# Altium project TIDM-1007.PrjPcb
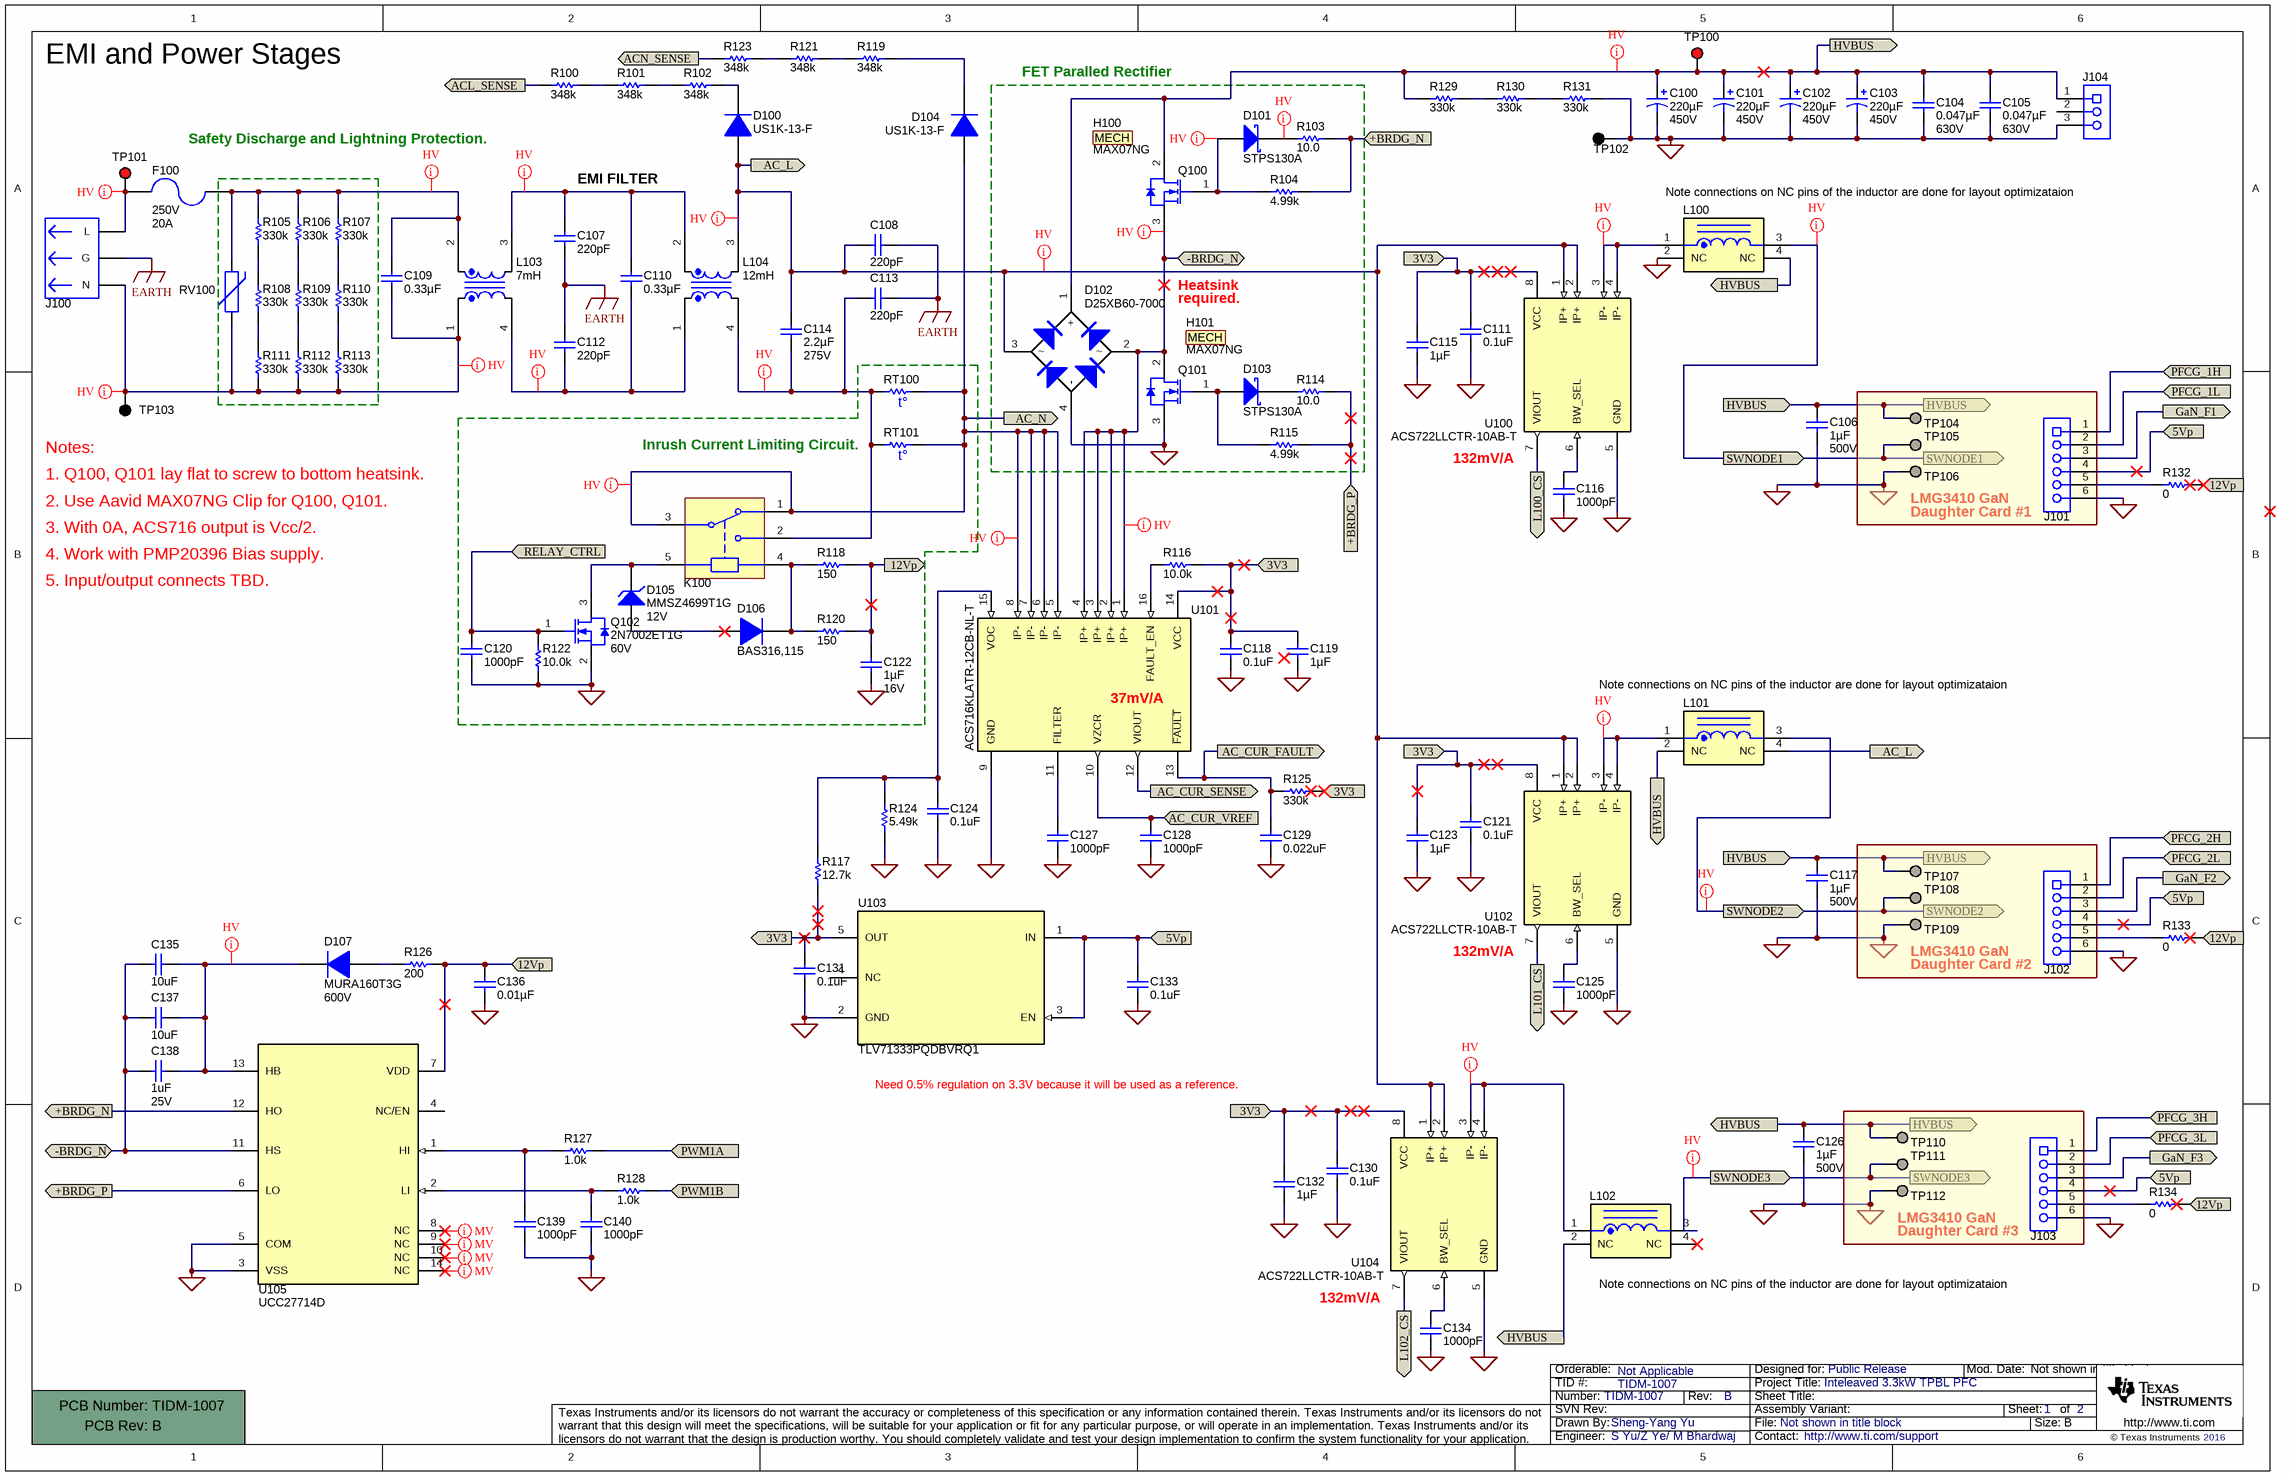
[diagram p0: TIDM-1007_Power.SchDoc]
TID: TIDM-1007; TechSupport: http://www.ti.com/support; SCH_Rev: B; PRJ_Title: Inteleaved 3.3kW TPBL PFC; PRJ_Number: TIDM-1007; PRJ_Engineer: S Yu/Z Ye/ M Bhardwaj; PRJ_Customer: Public Release; PCB_Rev: B; PCB_Layout: S Yu; EVM_orderable: Not Applicable; CopyrightYear: 2016
2 sheets, 193 parts. Net scope: flat (ports and power ports of the same name join across sheets).
Board file: TIDM-1007_PCB.PcbDoc
Sheets:
  TIDM-1007_Power.SchDoc
  TIDM-1007_Control.SchDoc

## Sheet TIDM-1007_Power.SchDoc
size 431 x 279 mm; Date: Not shown in title block; ApprovedBy: Not shown in title block; CheckedBy: Not shown in title block; Author: Not shown in title block; CompanyName: Not shown in title block; DrawnBy: Sheng-Yang Yu; Engineer: Not shown in title block; Organization: Not shown in title block; Address1: Not shown in title block; Address2: Not shown in title block; Address3: Not shown in title block; Address4: Not shown in title block; DocumentNumber: 1; Revision: Use project parameter SCH_Rev; SheetNumber: 1; SheetTotal: 2; PageSetup: Record=PageOptions¦CenterHorizontal=True¦CenterVertical=True¦PrintScale=1.00¦XCorrection=1.00¦YCorrection=1.00¦PrintKind=0¦BorderSize=5000000¦LeftOffset=0¦BottomOffset=0¦Orientation=2¦PaperLength=1000¦PaperWidth=1000¦Scale=100¦PaperSource=15¦PrintQuality=600¦MediaType=1¦DitherType=10¦PaperKind=Letter¦PrintScaleMode=1

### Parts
!PCB100  Printed Circuit Board  (value not drawn)  (mechanical)
C100  ValueDisplayed: 220µF  Value2: 450V  [KMW_2200x4000]  (hidden comment: EKMW451VSN221MP40S)
C101  ValueDisplayed: 220µF  Value2: 450V  [KMW_2200x4000]  (hidden comment: EKMW451VSN221MP40S)
C102  ValueDisplayed: 220µF  Value2: 450V  [KMW_2200x4000]  (hidden comment: EKMW451VSN221MP40S)
C103  ValueDisplayed: 220µF  Value2: 450V  [KMW_2200x4000]  (hidden comment: EKMW451VSN221MP40S)
C104  ValueDisplayed: 0.047µF  Value2: 630V  [1210_220]  (hidden comment: GRM32DR72J473KW01L)
C105  ValueDisplayed: 0.047µF  Value2: 630V  [1210_220]  (hidden comment: GRM32DR72J473KW01L)
C106  ValueDisplayed: 1µF  Value2: 500V  [B58031I_1084x785x450]  (hidden comment: B58031I5105M002)
C107  ValueDisplayed: 220pF  [DE1_600x400x900]  (hidden comment: DE1B3RA101KN4AN01F)
C108  ValueDisplayed: 220pF  [DE1_600x400x900]  (hidden comment: DE1B3RA101KN4AN01F)
C109  ValueDisplayed: 0.33µF  [B32923_15mm]  (hidden comment: B32923C3334M)
C110  ValueDisplayed: 0.33µF  [B32923_15mm]  (hidden comment: B32923C3334M)
C111  ValueDisplayed: 0.1uF  [0402]  (hidden comment: GRM155R70J104KA01D)
C112  ValueDisplayed: 220pF  [DE1_600x400x900]  (hidden comment: DE1B3RA101KN4AN01F)
C113  ValueDisplayed: 220pF  [DE1_600x400x900]  (hidden comment: DE1B3RA101KN4AN01F)
C114  ValueDisplayed: 2.2µF  Value2: 275V  [WCAP-FTX2_2600x1500x2500]  (hidden comment: 890324026034)
C115  ValueDisplayed: 1µF  [0603]  (hidden comment: GRM185R60J105KE26D)
C116  ValueDisplayed: 1000pF  [0603]  (hidden comment: 06035A102KAT2A)
C117  ValueDisplayed: 1µF  Value2: 500V  [B58031I_1084x785x450]  (hidden comment: B58031I5105M002)
C118  ValueDisplayed: 0.1uF  [0402]  (hidden comment: GRM155R70J104KA01D)
C119  ValueDisplayed: 1µF  [0603]  (hidden comment: GRM185R60J105KE26D)
C120  ValueDisplayed: 1000pF  [0603]  (hidden comment: GRM188R71C102KA01D)
C121  ValueDisplayed: 0.1uF  [0402]  (hidden comment: GRM155R70J104KA01D)
C122  ValueDisplayed: 1µF  Value2: 16V  [0805_HV]  (hidden comment: 0805YD105KAT2A)
C123  ValueDisplayed: 1µF  [0603]  (hidden comment: GRM185R60J105KE26D)
C124  ValueDisplayed: 0.1uF  [0402]  (hidden comment: GRM155R70J104KA01D)
C125  ValueDisplayed: 1000pF  [0603]  (hidden comment: 06035A102KAT2A)
C126  ValueDisplayed: 1µF  Value2: 500V  [B58031I_1084x785x450]  (hidden comment: B58031I5105M002)
C127  ValueDisplayed: 1000pF  [0402]  (hidden comment: GRM155R60J102KA01D)
C128  ValueDisplayed: 1000pF  [0402]  (hidden comment: GRM155R60J102KA01D)
C129  ValueDisplayed: 0.022uF  [0402]  (hidden comment: GRM155R70J223KA01D)
C130  ValueDisplayed: 0.1uF  [0402]  (hidden comment: GRM155R70J104KA01D)
C131  ValueDisplayed: 0.1uF  [0402]  (hidden comment: GRM155R70J104KA01D)
C132  ValueDisplayed: 1µF  [0603]  (hidden comment: GRM185R60J105KE26D)
C133  ValueDisplayed: 0.1uF  [0402]  (hidden comment: GRM155R70J104KA01D)
C134  ValueDisplayed: 1000pF  [0603]  (hidden comment: 06035A102KAT2A)
C135  ValueDisplayed: 10uF  [0805_HV]  (hidden comment: 0805YD106MAT2A)
C136  ValueDisplayed: 0.01µF  [0603]  (hidden comment: C0603X103K5RACTU)
C137  ValueDisplayed: 10uF  [0805_HV]  (hidden comment: 0805YD106MAT2A)
C138  ValueDisplayed: 1uF  Value2: 25V  [0603]  (hidden comment: C1608X7R1E105K080AB)
C139  ValueDisplayed: 1000pF  [0603]  (hidden comment: 06035A102KAT2A)
C140  ValueDisplayed: 1000pF  [0603]  (hidden comment: 06035A102KAT2A)
D100  US1K-13-F  [SMA]
D101  STPS130A  [SMA]
D102  D25XB60-7000  [5S]
D103  STPS130A  [SMA]
D104  US1K-13-F  [SMA]
D105  MMSZ4699T1G  value 12V  [SOD-123]
D106  BAS316,115  [sod-323]
D107  MURA160T3G  value 600V  [SMA]
F100  VAC_V: 250V  Irating_A: 20A  [FUSE_0325_Verical]  (hidden comment: 0325020.MXP)
H100  MAX07NG  (mechanical)
H101  MAX07NG  (mechanical)
J100  703W-00/54  [CONN_QUALTEK-703W-0054]  (value not drawn)  (mechanical)
J101  0448120024  [Molex_0448120024]  (value not drawn)
J102  0448120024  [Molex_0448120024]  (value not drawn)
J103  0448120024  [Molex_0448120024]  (value not drawn)
J104  282856-3  [TE_282856-3]  (value not drawn)
K100  875B-1CC-F-S-12VDC  [RELAY_875]  (value not drawn)
L100  G164005LF  [IND_7840-09-0014]  (value not drawn)
L101  G164005LF  [IND_7840-09-0014]  (value not drawn)
L102  G164005LF  [IND_7840-09-0014]  (value not drawn)
L103  ValueDisplayed: 7mH  [WE-CMBNC_XL]  (hidden comment: 7448051507)
L104  ValueDisplayed: 12mH  [WE-CMBNC_XL]  (hidden comment: 7448051012)
Q100  STY145N65M5  [TO-247]  (value not drawn)
Q101  STY145N65M5  [TO-247]  (value not drawn)
Q102  2N7002ET1G  value 60V  [SOT-23]
R100  value 348k  [0805_HV]  (hidden comment: RT0805BRD07348KL)
R101  value 348k  [0805_HV]  (hidden comment: RT0805BRD07348KL)
R102  value 348k  [0805_HV]  (hidden comment: RT0805BRD07348KL)
R103  ValueDisplayed: 10.0  [0805_HV]  (hidden comment: CRCW080510R0FKEA)
R104  ValueDisplayed: 4.99k  [0805_HV]  (hidden comment: ERJ-6ENF4991V)
R105  ValueDisplayed: 330k  [1206]  (hidden comment: CRCW1206330KJNEA)
R106  ValueDisplayed: 330k  [1206]  (hidden comment: CRCW1206330KJNEA)
R107  ValueDisplayed: 330k  [1206]  (hidden comment: CRCW1206330KJNEA)
R108  ValueDisplayed: 330k  [1206]  (hidden comment: CRCW1206330KJNEA)
R109  ValueDisplayed: 330k  [1206]  (hidden comment: CRCW1206330KJNEA)
R110  ValueDisplayed: 330k  [1206]  (hidden comment: CRCW1206330KJNEA)
R111  ValueDisplayed: 330k  [1206]  (hidden comment: CRCW1206330KJNEA)
R112  ValueDisplayed: 330k  [1206]  (hidden comment: CRCW1206330KJNEA)
R113  ValueDisplayed: 330k  [1206]  (hidden comment: CRCW1206330KJNEA)
R114  ValueDisplayed: 10.0  [0805_HV]  (hidden comment: CRCW080510R0FKEA)
R115  ValueDisplayed: 4.99k  [0805_HV]  (hidden comment: ERJ-6ENF4991V)
R116  value 10.0k  [0402]  (hidden comment: CRCW040210K0FKED)
R117  value 12.7k  [0402]  (hidden comment: CRCW040212K7FKED)
R118  ValueDisplayed: 150  [1206]  (hidden comment: CRCW1206150RJNEA)
R119  value 348k  [0805_HV]  (hidden comment: RT0805BRD07348KL)
R120  ValueDisplayed: 150  [1206]  (hidden comment: CRCW1206150RJNEA)
R121  value 348k  [0805_HV]  (hidden comment: RT0805BRD07348KL)
R122  value 10.0k  [0603]  (hidden comment: RC0603FR-0710KL)
R123  value 348k  [0805_HV]  (hidden comment: RT0805BRD07348KL)
R124  value 5.49k  [0402]  (hidden comment: CRCW04025K49FKED)
R125  value 330k  [0402]  (hidden comment: CRCW0402330KJNED)
R126  value 200  [0603]  (hidden comment: CRCW0603200RFKEA)
R127  value 1.0k  [0402]  (hidden comment: CRCW04021K00JNED)
R128  value 1.0k  [0402]  (hidden comment: CRCW04021K00JNED)
R129  ValueDisplayed: 330k  [1206]  (hidden comment: CRCW1206330KJNEA)
R130  ValueDisplayed: 330k  [1206]  (hidden comment: CRCW1206330KJNEA)
R131  ValueDisplayed: 330k  [1206]  (hidden comment: CRCW1206330KJNEA)
R132  ValueDisplayed: 0  [0603]  (hidden comment: CRCW06030000Z0EA)
R133  ValueDisplayed: 0  [0603]  (hidden comment: CRCW06030000Z0EA)
R134  ValueDisplayed: 0  [0603]  (hidden comment: CRCW06030000Z0EA)
RT100  B59751B0120A070  [TDK_B751]  (value not drawn)
RT101  B59751B0120A070  [TDK_B751]  (value not drawn)
RV100  S10K275E2  [VAR_S10K275E2]  (value not drawn)
TP100  Vo  [Keystone5000]  (value not drawn)
TP101  L  [Keystone5000]  (value not drawn)
TP102  PGND_PFC  [Keystone5001]  (value not drawn)
TP103  N  [Keystone5001]  (value not drawn)
TP104  Suggest using a net name here  [Mill-Max_0312-0-15-15-34-27-10-0]  (value not drawn)
TP105  Suggest using a net name here  [Mill-Max_0312-0-15-15-34-27-10-0]  (value not drawn)
TP106  Suggest using a net name here  [Mill-Max_0312-0-15-15-34-27-10-0]  (value not drawn)
TP107  Suggest using a net name here  [Mill-Max_0312-0-15-15-34-27-10-0]  (value not drawn)
TP108  Suggest using a net name here  [Mill-Max_0312-0-15-15-34-27-10-0]  (value not drawn)
TP109  Suggest using a net name here  [Mill-Max_0312-0-15-15-34-27-10-0]  (value not drawn)
TP110  Suggest using a net name here  [Mill-Max_0312-0-15-15-34-27-10-0]  (value not drawn)
TP111  Suggest using a net name here  [Mill-Max_0312-0-15-15-34-27-10-0]  (value not drawn)
TP112  Suggest using a net name here  [Mill-Max_0312-0-15-15-34-27-10-0]  (value not drawn)
U100  ACS722LLCTR-10AB-T  [SOIC-8]
U101  ACS716KLATR-12CB-NL-T  [SOIC-16]
U102  ACS722LLCTR-10AB-T  [SOIC-8]
U103  TLV71333PQDBVRQ1  [DBV0005A_N]
U104  ACS722LLCTR-10AB-T  [SOIC-8]
U105  UCC27714D  [D0014A_N]

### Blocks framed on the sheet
Inrush Current Limiting Circuit.: C120 C122 D105 D106 K100 Q102 R118 R120 R122 RT100 RT101

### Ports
3V3 (in), 3V3 (out), 5Vp (in), 12Vp (in), 12Vp (out), +BRDG_N, +BRDG_P, +BRDG_P (in), -BRDG_N (bidir), AC_CUR_FAULT, AC_CUR_SENSE, AC_CUR_VREF, AC_L, AC_N, ACL_SENSE (out), ACN_SENSE (out), GaN_F1 (out), GaN_F2 (out), GaN_F3 (out), HVBUS (in), HVBUS (out), L100_CS (out), L101_CS (out), L102_CS (out), PFCG_1H (in), PFCG_1L (in), PFCG_2H (in), PFCG_2L (in), PFCG_3H (in), PFCG_3L (in), PWM1A (in), PWM1B (in), RELAY_CTRL (in), SWNODE1 (out), SWNODE2 (out), SWNODE3 (out)

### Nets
EARTH: C107.2 C108.2 C112.1 C113.2 J100.3(G)
PGND: C100.2(-) C101.2(-) C102.2(-) C103.2(-) C104.1 C105.1 C106.1 C111.2 C115.2 C116.2 C117.1 C118.2 C119.2 C120.2 C121.2 C122.1 C123.2 C124.2 C125.2 C126.1 C127.2 C128.2 C129.1 C130.2 C131.2 C132.2 C133.2 C134.2 C136.2 C139.2 C140.2 D102.4(-) J101.6 J102.6 J103.6 J104.3 L100.2(NC) Q101.3(S) Q102.2(S) R122.1 R124.1 R131.1 TP102.1 TP106.1 TP109.1 TP112.1 U100.5(GND) U101.9(GND) U102.5(GND) U103.2(GND) U104.5(GND) U105.3(VSS) U105.5(COM)
3V3: C111.1 C115.1 C118.1 C119.1 C121.1 C123.1 C130.1 C131.1 C132.1 R116.2 R117.2 R125.1 U100.8(VCC) U101.14(VCC) U102.8(VCC) U103.5(OUT) U104.8(VCC) ; port 3V3
5Vp: C133.1 J101.4 J102.4 J103.4 U103.1(IN) U103.3(EN) ; port 5Vp
12Vp: C122.2 C136.1 R118.2 R120.2 R126.2 R132.2 R133.2 R134.2 U105.7(VDD) ; port 12Vp
+BRDG_N: R103.2 R104.2 U105.12(HO) ; port +BRDG_N
+BRDG_P: R114.2 R115.2 U105.6(LO) ; port +BRDG_P
-BRDG_N: C135.2 C137.2 C138.1 D102.2 Q100.3(S) Q101.2(D) U101.1(IP+) U101.2(IP+) U101.3(IP+) U101.4(IP+) U105.11(HS) ; port -BRDG_N
AC_CUR_FAULT: C129.2 R125.2 U101.13(~{FAULT}) ; port AC_CUR_FAULT
AC_CUR_SENSE: U101.12(VIOUT) ; port AC_CUR_SENSE
AC_CUR_VREF: C128.1 U101.10(VZCR) ; port AC_CUR_VREF
AC_L: C108.1 C114.1 D100.2(A) D102.3 L101.4(NC) L104.3 U100.1(IP+) U100.2(IP+) U102.1(IP+) U102.2(IP+) U104.1(IP+) U104.2(IP+) ; port AC_L
AC_N: D104.2(A) K100.1 K100.3 RT100.2 RT101.2 U101.5(IP-) U101.6(IP-) U101.7(IP-) U101.8(IP-) ; port AC_N
ACL_SENSE: R100.1 ; port ACL_SENSE
ACN_SENSE: R123.1 ; port ACN_SENSE
GaN_F1: J101.3 ; port GaN_F1
GaN_F2: J102.3 ; port GaN_F2
GaN_F3: J103.3 ; port GaN_F3
HVBUS: C100.1(+) C101.1(+) C102.1(+) C103.1(+) C104.2 C105.2 C106.2 C117.2 C126.2 D102.1(+) J104.1 L100.4(NC) L101.2(NC) L102.2(NC) Q100.2(D) R129.2 TP100.1 TP104.1 TP107.1 TP110.1 ; port HVBUS
L100_CS: U100.7(VIOUT) ; port L100_CS
L101_CS: U102.7(VIOUT) ; port L101_CS
L102_CS: U104.7(VIOUT) ; port L102_CS
PFCG_1H: J101.1 ; port PFCG_1H
PFCG_1L: J101.2 ; port PFCG_1L
PFCG_2H: J102.1 ; port PFCG_2H
PFCG_2L: J102.2 ; port PFCG_2L
PFCG_3H: J103.1 ; port PFCG_3H
PFCG_3L: J103.2 ; port PFCG_3L
PWM1A: R127.2 ; port PWM1A
PWM1B: R128.2 ; port PWM1B
RELAY_CTRL: C120.1 Q102.1(G) R122.2 ; port RELAY_CTRL
SWNODE1: L100.3 TP105.1 ; port SWNODE1
SWNODE2: L101.3 TP108.1 ; port SWNODE2
SWNODE3: L102.3 TP111.1 ; port SWNODE3
NetC107_1: C107.1 C110.1 L103.3 L104.2
NetC109_1: C109.1 F100.1 L103.2 R105.2 R106.2 R107.2 RV100.2
NetC109_2: C109.2 J100.2(N) L103.1 R111.1 R112.1 R113.1 RV100.1 TP103.1
NetC110_2: C110.2 C112.2 L103.4 L104.1
NetC113_1: C113.1 C114.2 K100.2 L104.4 RT100.1 RT101.1
NetC116_1: C116.1 U100.6(BW_SEL)
NetC124_1: C124.1 R117.1 R124.2 U101.15(VOC)
NetC125_1: C125.1 U102.6(BW_SEL)
NetC127_1: C127.1 U101.11(FILTER)
NetC134_1: C134.1 U104.6(BW_SEL)
NetC135_1: C135.1 C137.1 C138.2 D107.1(K) U105.13(HB)
NetC139_1: C139.1 R127.1 U105.1(HI)
NetC140_1: C140.1 R128.1 U105.2(LI)
NetD100_1: D100.1(K) R102.2
NetD101_1: D101.1(K) R103.1
NetD101_2: D101.2(A) Q100.1(G) R104.1
NetD103_1: D103.1(K) R114.1
NetD103_2: D103.2(A) Q101.1(G) R115.1
NetD104_1: D104.1(K) R119.2
NetD105_1: D105.1(K) K100.5 Q102.3(D)
NetD105_2: D105.2(A) D106.2(A)
NetD106_1: D106.1(K) K100.4 R118.1 R120.1
NetD107_2: D107.2(A) R126.1
NetF100_2: F100.2 J100.1(L) TP101.1
NetJ101_5: J101.5 R132.1
NetJ102_5: J102.5 R133.1
NetJ103_5: J103.5 R134.1
NetL100_1: L100.1 U100.3(IP-) U100.4(IP-)
NetL101_1: L101.1 U102.3(IP-) U102.4(IP-)
NetL102_1: L102.1 U104.3(IP-) U104.4(IP-)
NetR100_2: R100.2 R101.1
NetR101_2: R101.2 R102.1
NetR105_1: R105.1 R108.2
NetR106_1: R106.1 R109.2
NetR107_1: R107.1 R110.2
NetR108_1: R108.1 R111.2
NetR109_1: R109.1 R112.2
NetR110_1: R110.1 R113.2
NetR116_1: R116.1 U101.16(FAULT_EN)
NetR119_1: R119.1 R121.2
NetR121_1: R121.1 R123.2
NetR129_1: R129.1 R130.2
NetR130_1: R130.1 R131.2

Not connected (* = marked no-connect by the designer): J104 2; L102 4(NC)*; U103 4(NC); U105 4(NC/EN) 8(NC)* 9(NC)* 10(NC)* 14(NC)*

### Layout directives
net class HV: -BRDG_N, AC_L, AC_N, HVBUS, NetC107_1, NetC109_1, NetC109_2, NetC110_2, NetC113_1, NetC135_1, NetD101_1, NetD101_2, NetF100_2, NetL100_1, NetL101_1, NetL102_1, SWNODE1, SWNODE2, SWNODE3
net class MV: NetU105_8, NetU105_9, NetU105_10, NetU105_14

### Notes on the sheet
- EMI and Power Stages
- FET Paralled Rectifier
- Safety Discharge and Lightning Protection.
- (near C107) EMI FILTER
- Note connections on NC pins of the inductor are done for layout optimizataion
- Heatsink
- (near H101) required.
- (near TP103) Notes:
- 1. Q100, Q101 lay flat to screw to bottom heatsink.
- (near U100) 132mV/A
- (near TP106) LMG3410 GaN
- 3. With 0A, ACS716 output is Vcc/2.
- 4. Work with PMP20396 Bias supply.
- 2. Use Aavid MAX07NG Clip for Q100, Q101.
- Daughter Card #1
- 5. Input/output connects TBD.
- (near U101) 37mV/A
- (near L101) Note connections on NC pins of the inductor are done for layout optimizataion
- (near U102) 132mV/A
- (near TP109) LMG3410 GaN
- Daughter Card #2
- Need 0.5% regulation on 3.3V because it will be used as a reference.
- (near TP112) LMG3410 GaN
- Daughter Card #3
- (near U104) 132mV/A
- (near L102) Note connections on NC pins of the inductor are done for layout optimizataion

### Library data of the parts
!PCB100 = PCB: Manufacturer: Any; SymbolCreator: a0412235
C100-C103 = EKMW451VSN221MP40S: CAP, AL, 220 µF, 450 V, +/- 20%, TH; Manufacturer: Chemi-Con; Polarized: Y; CompType: Capacitor; Value: 220uF; U/M: EA; Cap_F: 0.00022; Tolerance_%: 20; Value1: Unknown; VDC_V: 450; IRMS_A: 1.15; TaMin_C: -25; TaMax_C: 105; Cap_Case: 22x40mm; AEC Category: Q200; AEC Qualified: N
C104 C105 = GRM32DR72J473KW01L: CAP, CERM, 0.047 µF, 630 V, +/- 10%, X7R, 1210; Manufacturer: MuRata; Polarized: N; CompType: Capacitor; Value: 0.047uF; U/M: EA; Cap_F: 0.000000047; Tolerance_%: 10; Value1: Unknown; VDC_V: 630; TaMin_C: -55; TaMax_C: 125; Cap_Case: 1210; SizeArea_mm2: 8; SizeAreaWB_mm2: 14.7; SizeX_mm: 3.2; SizeY_mm: 2.5; SizeZ_mm: 2.2; AEC Category: Q200
C106 C117 C126 = B58031I5105M002: CAP, CERM, 1 µF, 500 V, +/- 20%, B58031, AEC-Q200 Grade 0, 6.84x7.85mm; Manufacturer: TDK; Polarized: N; CompType: Capacitor; Value: 1uF; U/M: EA; Cap_F: 0.000001; Tolerance_%: 20; Value1: Unknown; VDC_V: 500; IRMS_A: 7.5; TaMin_C: -40; TaMax_C: 150; Cap_Case: 10.84x7.85x4.5mm; SizeArea_mm2: 85.094; SizeAreaWB_mm2: 126.474; SizeX_mm: 10.84; SizeY_mm: 7.85; SizeZ_mm: 4.5; AEC Category: Q200; AEC Qualified: Y; AEC Grade: 0
C107 C108 C112 C113 = CMP-0077651-2: CAP CER 220PF 250V RAD; PartNumber: DE1B3RA221KN4AN01F; Manufacturer: MuRata; TaMax_C: 125°C; SizeX_mm: 10.6; SizeY_mm: 4.0; TaMin_C: -40°C; CompType: Capacitor; SizeZ_mm: 9.0; AEC Qualified: N; SizeArea_mm2: 42.4; AEC Category: Q200; SizeAreaWB_mm2: 75.6; U/M: EA; Tolerance_%: 10%; TempCo: B; Cap_Case: 6x4x9mm; Cap_F: 100pF; AC_Safety: X1Y1; VAC_X: 440; VAC_Y: 250
C109 C110 = B32923C3334M: CAP, Film, 0.33 µF, 630 V,+/- 20%, TH; Manufacturer: TDK; Polarized: N; CompType: Capacitor; Value: 0.33uF; U/M: EA; Cap_F: 0.00000033; Tolerance_%: 20; VDC_V: 630; Value2: 630V; TaMax_C: 110; SizeAreaWB_mm2: 228; SizeArea_mm2: 159; SizeX_mm: 6; SizeY_mm: 26.5; SizeZ_mm: 15; AEC Category: Q200
C111 C118 C121 C124 C130 C131 C133 = GRM155R70J104KA01D: CAP, CERM, 0.1uF, 6.3V, +/-10%, X7R, 0402; Manufacturer: MuRata; Polarized: N; CompType: Capacitor; U/M: EA; Cap_F: 0.0000001; Tolerance_%: 10; Value1: Unknown; VDC_V: 6.3; TaMin_C: -55; TaMax_C: 125
C114 = 890324026034: CAP, Film, 2.2 µF, 275 V, +/- 10%, TH; Manufacturer: Wurth Elektronik; Polarized: N; CompType: Capacitor; Value: 2.2uF; U/M: EA; Cap_F: 0.0000022; Tolerance_%: 10; Value1: Unknown; VDC_V: 275; TaMin_C: -40; TaMax_C: 105; Cap_Case: 26x15x25mm; AEC Category: Q200
C115 C119 C123 C132 = GRM185R60J105KE26D: CAP, CERM, 1uF, 6.3V, +/-10%, X5R, 0603; Manufacturer: MuRata; Polarized: N; CompType: Capacitor; U/M: EA; Cap_F: 0.000001; Tolerance_%: 10; Value1: Unknown; VDC_V: 6.3; TaMin_C: -55; TaMax_C: 85
C116 C125 C134 C139 C140 = 06035A102KAT2A: CAP, CERM, 1000 pF, 50 V, +/- 10%, C0G/NP0, 0603; Manufacturer: AVX; Polarized: N; CompType: Capacitor; Value: 1000pF; U/M: EA; Cap_F: 0.000000001; Tolerance_%: 10; ESR_ohm: 0.048; Value1: 0.048 ohm; VDC_V: 50; Value2: 50V; TaMin_C: -55; TaMax_C: 125; SizeArea_mm2: 1.28; SizeAreaWB_mm2: 4.68; SizeX_mm: 1.6; SizeY_mm: 0.8; SizeZ_mm: 1; AEC Category: Q200
C120 = GRM188R71C102KA01D: CAP, CERM, 1000pF, 16V, +/-10%, X7R, 0603; Manufacturer: MuRata; Polarized: N; CompType: Capacitor; U/M: EA; Cap_F: 0.000000001; Tolerance_%: 10; Value1: Unknown; VDC_V: 16; TaMin_C: -55; TaMax_C: 125
C122 = 0805YD105KAT2A: CAP, CERM, 1uF, 16V, +/-10%, X5R, 0805; Manufacturer: AVX; Polarized: N; CompType: Capacitor; U/M: EA; Cap_F: 0.000001; Tolerance_%: 10; ESR_Ohm: 0.012; Value1: 0.012 ohm; VDC_V: 16; TaMin_C: -55; TaMax_C: 85; Cap_Case: 0805
C127 C128 = GRM155R60J102KA01D: CAP, CERM, 1000pF, 6.3V, +/-10%, X5R, 0402; Manufacturer: MuRata; Polarized: N; CompType: Capacitor; U/M: EA; Cap_F: 0.000000001; Tolerance_%: 10; Value1: Unknown; VDC_V: 6.3; TaMin_C: -55; TaMax_C: 85
C129 = GRM155R70J223KA01D: CAP, CERM, 0.022uF, 6.3V, +/-10%, X7R, 0402; Manufacturer: MuRata; Polarized: N; CompType: Capacitor; U/M: EA; Cap_F: 0.000000022; Tolerance_%: 10; Value1: Unknown; VDC_V: 6.3; TaMin_C: -55; TaMax_C: 125
C135 C137 = 0805YD106MAT2A: CAP, CERM, 10uF, 16V, +/-20%, X5R, 0805; Manufacturer: AVX; Polarized: N; CompType: Capacitor; U/M: EA; Cap_F: 0.00001; Tolerance_%: 20; Value1: Unknown; VDC_V: 16; TaMin_C: -55; TaMax_C: 85; Cap_Case: 0805
C136 = C0603X103K5RACTU: CAP, CERM, 0.01uF, 50V, +/-10%, X7R, 0603; Manufacturer: Kemet; Polarized: N; CompType: Capacitor; U/M: EA; Cap_F: 0.00000001; Tolerance_%: 10; Value1: Unknown; VDC_V: 50; TaMin_C: -55; TaMax_C: 125
C138 = C1608X7R1E105K080AB: CAP, CERM, 1uF, 25V, +/-10%, X7R, 0603; Manufacturer: TDK; Polarized: N; CompType: Capacitor; U/M: EA; Cap_F: 0.000001; Tolerance_%: 10; Value1: Unknown; VDC_V: 25; TaMin_C: -55; TaMax_C: 125
D100 D104 = US1K-13-F: Diode, Fast Rectifier, 800 V, 1 A, SMA; Manufacturer: Diodes Inc.; U/M: EA; Vf_V: 1.7; Value: 800V; Value1: 1A; Value2: 1.7V; Io_A: 1; Vr_V: 800; TJmax_C: 150; AEC Category: Q101
D101 D103 = STPS130A: Diode, Schottky, 30 V, 1 A, SMA; Manufacturer: STMicroelectronics; U/M: EA; Vf_V: 0.46; Value: 30V; Value1: 1A; Value2: 0.46V; Io_A: 1; Vr_V: 30; TJmax_C: 150; AEC Category: Q101
D102 = D25XB60-7000: Diode, Switching-Bridge, 600 V, 3.5 A, TH; Manufacturer: Shindengen; U/M: EA; Vf_V: 1.05; Value: 600V; Value1: 3.5A; Value2: 1.05V; Io_A: 3.5; Vr_V: 600; TJmax_C: 150
D105 = MMSZ4699T1G: Diode, Zener, 12 V, 500 mW, SOD-123; Manufacturer: ON Semiconductor; SymbolCreator: a0412235; U/M: EA; Power_W: 0.5; Vz_V: 12; Value1: 0.5W; RJA_CperW: 340
D106 = BAS316,115: Diode, Ultrafast, 100 V, 0.25 A, SOD-323; Manufacturer: NXP Semiconductor; U/M: EA; Vf_V: 1.4; Value: 100V; Value1: 0.25A; Value2: 1.4V; Io_A: 0.25; Vr_V: 100; TJmax_C: 150
D107 = MURA160T3G: Diode, Ultrafast, 600V, 1A, SMA; Manufacturer: ON Semiconductor; U/M: EA; Vf_V: 1.05; Value2: 1.05V; Io_A: 1; Vr_V: 600; TJmax_C: 175
F100 = 0325020.MXP: Fuse, 20 A, 250 VAC, 60 VDC, TH; Manufacturer: Littelfuse; VDC_V: 60; Interrupt_AC: 400; Rtyp_Ohm: 0.0034; MeltingTyp: 575
H100 H101 = MAX08NG: MAX CLIP TO-220; Manufacturer: Aavid; SymbolCreator: codlsc
J100 = 703W-00/54: AC Receptacle, 10A 250VAC; Manufacturer: Qualtek Electronics Corporation; SymbolCreator: a0799628; CompType: Connector; U/M: EA
J101-J103 = 0448120024: Receptacle, 2.54mm, 6x1, Gold, TH; Manufacturer: Molex; SymbolCreator: a0411947; Pitch_mm: 2.54; Gender: Female; Row_Count: 1
J104 = 282856-3: Receptacle, 3x1, 5mm, R/A, TH; Manufacturer: TE Connectivity; SymbolCreator: a0412235; CompType: Terminal Block; Pitch_mm: 5; Gender: Female; Row_Count: 1; ContactFinish: Tin; Current_A: 24; Voltage_V: 300; Cert_UL: Y
K100 = 875B-1CC-F-S-12VDC: Relay, SPDT ( 1 Form C), 16A, 12 VDC, TH; Manufacturer: SONG CHUAN; SymbolCreator: Altium; Coil Current: 30 mA; Coil Power: 360 mW; Coil Resistance: 400 ohms; Coil Voltage: 12 VDC; Turn Off Voltage (Min): 0.6 VDC; Turn On Voltage (Max): 9 VDC; Time Operate (s): 0.015; Time Release (s): 0.01
L100 L102 = CMP-0074586-1: Inductor, Toroid, 0.065 ohm, TH; Manufacturer: GCI Technologies; SizeAreaWB_mm2: 1112.5; DCR_ohm: 0.057; SizeZ_mm: 44.5; SizeX_mm: 23.0; SizeY_mm: 42.5; Value2: A; SizeArea_mm2: 977.5; AEC Qualified: N; AEC Category: Q200
L101 = CMP-0074586-1: Inductor, Toroid, 0.065 ohm, TH; Manufacturer: GCI Technologies; SizeAreaWB_mm2: 1112.5; DCR_ohm: 0.065; SizeZ_mm: 44.5; SizeX_mm: 23.0; SizeY_mm: 42.5; Value2: A; SizeArea_mm2: 977.5; AEC Qualified: N; AEC Category: Q200
L103 = 7448052303: COMMON MODE CHOKE; Manufacturer: Wurth Elektronik; SymbolCreator: a0799628; Value: 7mH; CompType: Coupled Inductor
L104 = 7448052303: CMC 12MH 10A 2LN TH; Manufacturer: Wurth Elektronik; SymbolCreator: a0799628; CompType: Coupled Inductor
Q100 Q101 = STY105NM50N: MOSFET N-CH 650V 138A MAX247; Manufacturer: STMicroelectronics; Alternate Manufacturer: None; U/M: EA; ChType: N; VdsMax_V: 650; Value1: ? ohm; Value2: 326 nC; QgTyp_nC: 326; IdsMax_A: 110; AEC Category: Q101
Q102 = 2N7002ET1G: MOSFET, N-CH, 60V, 0.26A, SOT-23; Manufacturer: ON Semiconductor; Alternate Manufacturer: None; U/M: EA; ChType: N; VdsMax_V: 60; Value1: 3 ohm; Rdson45_Ohm: 3; Value2: 0.81 nC; QgTyp_nC: 0.81; Vgs_V: 20; IdsMax_A: 0.26
R100-R102 R119 R121 R123 = RT0805BRD07348KL: RES, 348k ohm, 0.1%, 0.125W, 0805; Manufacturer: Yageo America; CompType: Resistor; Res_ohm: 348000; Tolerance_%: 0.1; Power_W: 0.125; VDC_V: 150; TempCo: 25 ppm/C; EIA_Code: E192; U/M: EA
R103 R114 = CRCW080510R0FKEA: RES, 10.0, 1%, 0.125 W, 0805; Manufacturer: Vishay-Dale; CompType: Resistor; Value: 10.0; Res_ohm: 10; Value_Code: 10R0; Tolerance_%: 1; Power_W: 0.125; Value2: 0.125W; VDC_V: 150; TempCo: 100 ppm/C; EIA_Code: E96; U/M: EA
R104 R115 = ERJ-6ENF4991V: RES, 4.99 k, 1%, 0.125 W, 0805; Manufacturer: Panasonic; CompType: Resistor; Value: 4.99k; Res_ohm: 4990; Value_Code: 4k99; Tolerance_%: 1; Power_W: 0.125; Value2: 0.125W; TempCo: 100 ppm/C; EIA_Code: E96; U/M: EA; AEC Category: Q200
R105-R113 R129-R131 = CRCW1206330KJNEA: RES, 330 k, 5%, 0.25 W, 1206; Manufacturer: Vishay-Dale; CompType: Resistor; Value: 330k; Res_ohm: 330000; Tolerance_%: 5; Power_W: 0.25; Value2: 0.25W; VDC_V: 200; TempCo: 200 ppm/C; SizeArea_mm2: 5.12; SizeX_mm: 3.2; SizeY_mm: 1.6; SizeZ_mm: 1.35; EIA_Code: E24; U/M: EA; AEC Category: Q200
R116 = CRCW040210K0FKED: RES, 10.0k ohm, 1%, 0.063W, 0402; Manufacturer: Vishay-Dale; CompType: Resistor; Res_ohm: 10000; Value_Code: 10k0; Tolerance_%: 1; Power_W: 0.063; VDC_V: 50; TempCo: 100 ppm/C; EIA_Code: E96; U/M: EA
R117 = CRCW040212K7FKED: RES, 12.7k ohm, 1%, 0.063W, 0402; Manufacturer: Vishay-Dale; CompType: Resistor; Res_ohm: 12700; Value_Code: 12k7; Tolerance_%: 1; Power_W: 0.063; VDC_V: 50; TempCo: 100 ppm/C; EIA_Code: E96; U/M: EA
R118 R120 = CRCW1206150RJNEA: RES, 150, 5%, 0.25 W, 1206; Manufacturer: Vishay-Dale; CompType: Resistor; Value: 150; Value_Code: 150R; Tolerance_%: 5; Power_W: 0.25; Value2: 0.25W; VDC_V: 200; TempCo: 200 ppm/C; EIA_Code: E24; U/M: EA
R122 = RC0603FR-0710KL: RES, 10.0k ohm, 1%, 0.1W, 0603; Manufacturer: Yageo America; CompType: Resistor; Res_ohm: 10000; Value_Code: 10k0; Tolerance_%: 1; Power_W: 0.1; VDC_V: 150; TempCo: 200 ppm/C; EIA_Code: E96; U/M: EA
R124 = CRCW04025K49FKED: RES, 5.49k ohm, 1%, 0.063W, 0402; Manufacturer: Vishay-Dale; CompType: Resistor; Res_ohm: 5490; Value_Code: 5k49; Tolerance_%: 1; Power_W: 0.063; VDC_V: 50; TempCo: 100 ppm/C; EIA_Code: E96; U/M: EA
R125 = CRCW0402330KJNED: RES, 330k ohm, 5%, 0.063W, 0402; Manufacturer: Vishay-Dale; CompType: Resistor; Res_ohm: 330000; Tolerance_%: 5; Power_W: 0.063; VDC_V: 50; TempCo: 200 ppm/C; EIA_Code: E24; U/M: EA
R126 = CRCW0603200RFKEA: RES, 200 ohm, 1%, 0.1W, 0603; Manufacturer: Vishay-Dale; CompType: Resistor; Value_Code: 200R; Tolerance_%: 1; Power_W: 0.1; VDC_V: 75; TempCo: 100 ppm/C; EIA_Code: E96; U/M: EA
R127 R128 = CRCW04021K00JNED: RES, 1.0k ohm, 5%, 0.063W, 0402; Manufacturer: Vishay-Dale; CompType: Resistor; Res_ohm: 1000; Value_Code: 1k00; Tolerance_%: 5; Power_W: 0.063; VDC_V: 50; TempCo: 200 ppm/C; EIA_Code: E24; U/M: EA
R132-R134 = CRCW06030000Z0EA: RES, 0, 5%, 0.1 W, 0603; Manufacturer: Vishay-Dale; CompType: Resistor; Value: 0; Value_Code: 0000; Tolerance_%: 5; Power_W: 0.1; Value2: 0.1W; VDC_V: 75; TempCo: 200 ppm/C; SizeArea_mm2: 1.28; SizeX_mm: 1.6; SizeY_mm: 0.8; SizeZ_mm: 1; EIA_Code: E24; U/M: EA; AEC Category: Q200
RT100 = B59751B0120A070: Thermistor NTC, 50 ohm, 25%, D12.5xH16.5mm; Manufacturer: TDK; Value: 50; Tolerance_%: 25; TaMin_C: -40; TaMax_C: 125; U/M: EA
RT101 = B59751B0120A070: Thermistor NTC, 50 ohm, 25%, D12.5xH16.5mm; Manufacturer: TDK; Value: 50 ohm; Tolerance_%: 25; TaMin_C: -40; TaMax_C: 125; U/M: EA
RV100 = S10K275E2: Varistor 275V RMS 10MM Radial, TH; Manufacturer: EPCOS Inc; SymbolCreator: a0412235
TP100 TP101 = 5000: Test Point, Miniature, Red, TH; Manufacturer: Keystone; CompType: Test Point Loop; U/M: EA
TP102 TP103 = 5001: Test Point, Miniature, Black, TH; Manufacturer: Keystone; CompType: Test Point Loop; U/M: EA
TP104-TP112 = 0312-0-15-15-34-27-10-0: Pin Receptacle, .032-.046" .075" Dia, Gold, TH; Manufacturer: Mill-Max; Gender: Female
U100 U102 U104 = ACS722LLCTR-10AB-T: High Accuracy, Galvanically Isolated Current Sensor IC, SOIC-8; Manufacturer: Allegro Microsystems Inc; SymbolCreator: Altium; SizeAreaWB_mm2: 55.131; SizeArea_mm2: 29.351; SizeX_mm: 5.99; SizeY_mm: 4.9; SizeZ_mm: 1.75
U101 = ACS716KLATR-12CB-NL-T: SENSOR CURRENT HALL 12.5A AC/DC; Manufacturer: Allegro Microsystems Inc; SymbolCreator: Altium
U103 = TLV71333PQDBVRQ1: Capacitor-Free, 150-mA, Low-Dropout Regulator with Foldback Current Limit for Portable Devices, DBV0005A; Manufacturer: Texas Instruments; SymbolCreator: Altium; SizeArea_mm2: 8.12; SizeAreaWB_mm2: 14.82; SizeX_mm: 2.8; SizeY_mm: 2.9; SizeZ_mm: 1.45; CompType: IC; U/M: EA
U105 = UCC27714D: High-Speed,4A, 600V High-side Low-side Gate Driver Device, D0014A; Manufacturer: Texas Instruments; SymbolCreator: a0411947; CompType: IC; U/M: EA

## Sheet TIDM-1007_Control.SchDoc
size 431 x 279 mm; Date: Not shown in title block; ApprovedBy: Not shown in title block; CheckedBy: Not shown in title block; Author: Not shown in title block; CompanyName: Not shown in title block; Engineer: Not shown in title block; Organization: Not shown in title block; Address1: Not shown in title block; Address2: Not shown in title block; Address3: Not shown in title block; Address4: Not shown in title block; DocumentNumber: 2; Revision: Use project parameter SCH_Rev; SheetNumber: 2; SheetTotal: 2; PageSetup: Record=PageOptions¦CenterHorizontal=True¦CenterVertical=True¦PrintScale=1.00¦XCorrection=1.00¦YCorrection=1.00¦PrintKind=0¦BorderSize=5000000¦LeftOffset=0¦BottomOffset=0¦Orientation=2¦PaperLength=1000¦PaperWidth=1000¦Scale=100¦PaperSource=15¦PrintQuality=600¦MediaType=1¦DitherType=10¦PaperKind=Letter¦PrintScaleMode=1
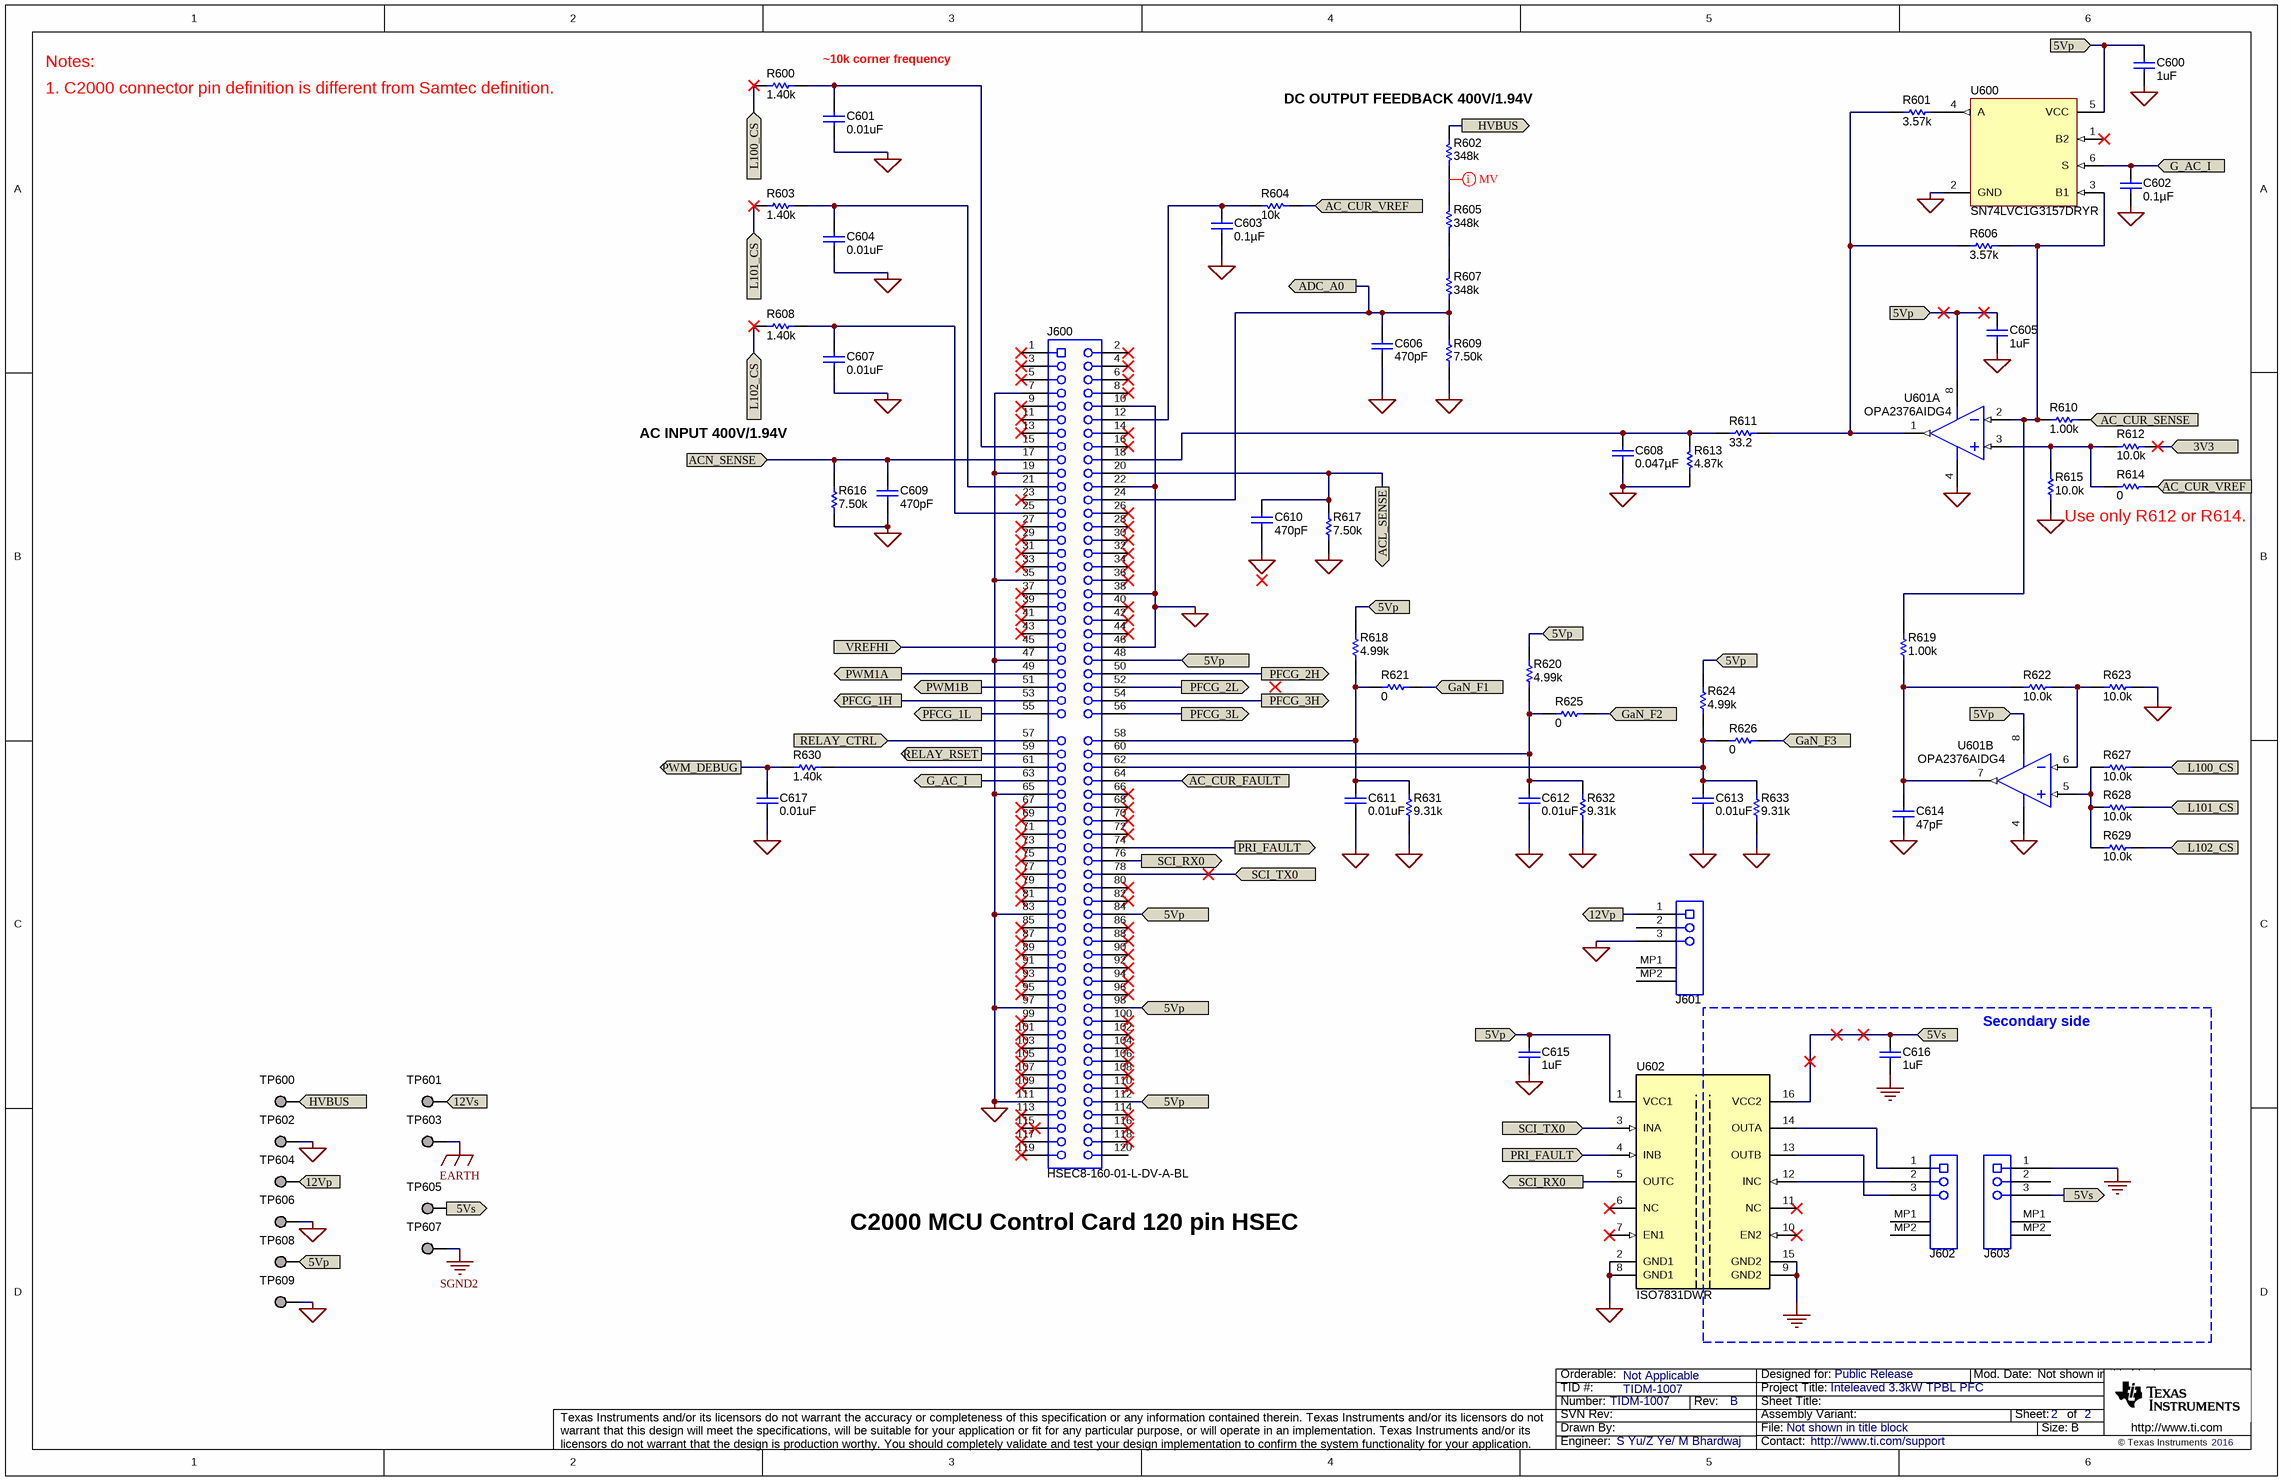
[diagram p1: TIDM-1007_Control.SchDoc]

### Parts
C600  ValueDisplayed: 1uF  [0603]  (hidden comment: C1608X7R1E105K080AB)
C601  ValueDisplayed: 0.01uF  [0402]  (hidden comment: GRM155R70J103KA01D)
C602  ValueDisplayed: 0.1µF  [0402]  (hidden comment: GCM155R71C104KA55D)
C603  ValueDisplayed: 0.1µF  [0402]  (hidden comment: GRM155R60J104KA01D)
C604  ValueDisplayed: 0.01uF  [0402]  (hidden comment: GRM155R70J103KA01D)
C605  ValueDisplayed: 1uF  [0603]  (hidden comment: C1608X7R1E105K080AB)
C606  ValueDisplayed: 470pF  [0402]  (hidden comment: CGA2B2X7R1H471K050BA)
C607  ValueDisplayed: 0.01uF  [0402]  (hidden comment: GRM155R70J103KA01D)
C608  ValueDisplayed: 0.047µF  [0402]  (hidden comment: C1005X5R1A473K050BA)
C609  ValueDisplayed: 470pF  [0402]  (hidden comment: CGA2B2X7R1H471K050BA)
C610  ValueDisplayed: 470pF  [0402]  (hidden comment: CGA2B2X7R1H471K050BA)
C611  ValueDisplayed: 0.01uF  [0402]  (hidden comment: GRM155R70J103KA01D)
C612  ValueDisplayed: 0.01uF  [0402]  (hidden comment: GRM155R70J103KA01D)
C613  ValueDisplayed: 0.01uF  [0402]  (hidden comment: GRM155R70J103KA01D)
C614  ValueDisplayed: 47pF  [0402]  (hidden comment: GRM1555C1E470JA01D)
C615  ValueDisplayed: 1uF  [0603]  (hidden comment: C1608X7R1E105K080AB)
C616  ValueDisplayed: 1uF  [0603]  (hidden comment: C1608X7R1E105K080AB)
C617  ValueDisplayed: 0.01uF  [0402]  (hidden comment: GRM155R70J103KA01D)
J600  HSEC8-160-01-L-DV-A-BL  [controlCARD-120HSEC]
J601  DF59-3S-2V(51)  [Hirose_DF59-3S-2V_51]  (value not drawn)
J602  DF59-3S-2V(51)  [Hirose_DF59-3S-2V_51]  (value not drawn)
J603  DF59-3S-2V(51)  [Hirose_DF59-3S-2V_51]  (value not drawn)
R600  value 1.40k  [0402]  (hidden comment: CRCW04021K40FKED)
R601  ValueDisplayed: 3.57k  [0402]  (hidden comment: CRCW04023K57FKED)
R602  value 348k  [0805_HV]  (hidden comment: RT0805BRD07348KL)
R603  value 1.40k  [0402]  (hidden comment: CRCW04021K40FKED)
R604  value 10k  [0402]  (hidden comment: CRCW040210K0JNED)
R605  value 348k  [0805_HV]  (hidden comment: RT0805BRD07348KL)
R606  ValueDisplayed: 3.57k  [0402]  (hidden comment: CRCW04023K57FKED)
R607  value 348k  [0805_HV]  (hidden comment: RT0805BRD07348KL)
R608  value 1.40k  [0402]  (hidden comment: CRCW04021K40FKED)
R609  ValueDisplayed: 7.50k  [0805_HV]  (hidden comment: CRCW08057K50FKEA)
R610  ValueDisplayed: 1.00k  [0402]  (hidden comment: CRCW04021K00FKED)
R611  ValueDisplayed: 33.2  [0402]  (hidden comment: CRCW040233R2FKED)
R612  ValueDisplayed: 10.0k  [0402]  (hidden comment: CRCW040210K0FKED)
R613  ValueDisplayed: 4.87k  [0402]  (hidden comment: ERA-2AEB4871X)
R614  ValueDisplayed: 0  [0402]  (hidden comment: CRCW04020000Z0ED)
R615  ValueDisplayed: 10.0k  [0402]  (hidden comment: CRCW040210K0FKED)
R616  ValueDisplayed: 7.50k  [0402]  (hidden comment: CRCW04027K50FKED)
R617  ValueDisplayed: 7.50k  [0402]  (hidden comment: CRCW04027K50FKED)
R618  ValueDisplayed: 4.99k  [0402]  (hidden comment: CRCW04024K99FKED)
R619  ValueDisplayed: 1.00k  [0402]  (hidden comment: CRCW04021K00FKED)
R620  ValueDisplayed: 4.99k  [0402]  (hidden comment: CRCW04024K99FKED)
R621  ValueDisplayed: 0  [0402]  (hidden comment: CRCW04020000Z0ED)
R622  ValueDisplayed: 10.0k  [0402]  (hidden comment: CRCW040210K0FKED)
R623  ValueDisplayed: 10.0k  [0402]  (hidden comment: CRCW040210K0FKED)
R624  ValueDisplayed: 4.99k  [0402]  (hidden comment: CRCW04024K99FKED)
R625  ValueDisplayed: 0  [0402]  (hidden comment: CRCW04020000Z0ED)
R626  ValueDisplayed: 0  [0402]  (hidden comment: CRCW04020000Z0ED)
R627  ValueDisplayed: 10.0k  [0402]  (hidden comment: CRCW040210K0FKED)
R628  ValueDisplayed: 10.0k  [0402]  (hidden comment: CRCW040210K0FKED)
R629  ValueDisplayed: 10.0k  [0402]  (hidden comment: CRCW040210K0FKED)
R630  value 1.40k  [0402]  (hidden comment: CRCW04021K40FKED)
R631  ValueDisplayed: 9.31k  [0402]  (hidden comment: CRCW04029K31FKED)
R632  ValueDisplayed: 9.31k  [0402]  (hidden comment: CRCW04029K31FKED)
R633  ValueDisplayed: 9.31k  [0402]  (hidden comment: CRCW04029K31FKED)
TP600  Suggest using a net name here  [Mill-Max_0312-0-15-15-34-27-10-0]  (value not drawn)
TP601  Suggest using a net name here  [Mill-Max_0312-0-15-15-34-27-10-0]  (value not drawn)
TP602  Suggest using a net name here  [Mill-Max_0312-0-15-15-34-27-10-0]  (value not drawn)
TP603  Suggest using a net name here  [Mill-Max_0312-0-15-15-34-27-10-0]  (value not drawn)
TP604  Suggest using a net name here  [Mill-Max_0312-0-15-15-34-27-10-0]  (value not drawn)
TP605  Suggest using a net name here  [Mill-Max_0312-0-15-15-34-27-10-0]  (value not drawn)
TP606  Suggest using a net name here  [Mill-Max_0312-0-15-15-34-27-10-0]  (value not drawn)
TP607  Suggest using a net name here  [Mill-Max_0312-0-15-15-34-27-10-0]  (value not drawn)
TP608  Suggest using a net name here  [Mill-Max_0312-0-15-15-34-27-10-0]  (value not drawn)
TP609  Suggest using a net name here  [Mill-Max_0312-0-15-15-34-27-10-0]  (value not drawn)
U600  SN74LVC1G3157DRYR  [DRY0006A]
U601  OPA2376AIDG4  [D0008A_N]  (parts A,B of 2)
U602  ISO7831DWR  [DW0016B_N]

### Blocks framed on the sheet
Secondary side: C616 J602 J603 U602

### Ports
3V3 (in), 5Vp (in), 5Vs (in), 5Vs (out), 12Vp (in), 12Vp (out), 12Vs (in), AC_CUR_FAULT (in), AC_CUR_SENSE, AC_CUR_VREF, ACL_SENSE, ACN_SENSE, ADC_A0 (out), G_AC_I (in), G_AC_I (out), GaN_F1 (in), GaN_F2 (in), GaN_F3 (in), HVBUS (out), L100_CS (in), L101_CS (in), L102_CS (in), PFCG_1H (out), PFCG_1L (out), PFCG_2H (out), PFCG_2L (out), PFCG_3H (out), PFCG_3L (out), PRI_FAULT (in), PRI_FAULT (out), PWM1A, PWM1B, PWM_DEBUG (out), RELAY_CTRL, RELAY_RSET (out), SCI_RX0 (out), SCI_TX0 (in), VREFHI (in)

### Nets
EARTH: TP603.1
PGND: C600.1 C601.2 C602.2 C603.1 C604.2 C605.1 C606.2 C607.2 C608.2 C609.2 C610.2 C611.2 C612.2 C613.2 C614.2 C615.1 C617.2 J600.7 J600.10 J600.19 J600.22 J600.35 J600.38 J600.46 J600.47 J600.65 J600.83 J600.97 J600.111 J601.3 R609.1 R613.1 R615.1 R616.1 R617.1 R623.2 R631.1 R632.1 R633.1 TP602.1 TP606.1 TP609.1 U600.2(GND) U601.4(V-) U602.2(GND1) U602.8(GND1)
SGND2: C616.1 J603.1 TP607.1 U602.9(GND2) U602.15(GND2)
3V3: R612.2 ; port 3V3
5Vp: C600.2 C605.2 C615.2 J600.48 J600.84 J600.98 J600.112 R618.2 R620.2 R624.2 TP608.1 U600.5(VCC) U601.8(V+) U602.1(VCC1) ; port 5Vp
5Vs: C616.2 J603.3 TP605.1 U602.16(VCC2) ; port 5Vs
12Vp: J601.1 TP604.1 ; port 12Vp
12Vs: TP601.1 ; port 12Vs
AC_CUR_FAULT: J600.64 ; port AC_CUR_FAULT
AC_CUR_SENSE: R610.1 ; port AC_CUR_SENSE
AC_CUR_VREF: R604.2 R614.2 ; port AC_CUR_VREF
ACL_SENSE: C610.1 J600.20 R617.2 ; port ACL_SENSE
ACN_SENSE: C609.1 J600.17 R616.2 ; port ACN_SENSE
ADC_A0: C606.1 J600.24 R607.1 R609.2 ; port ADC_A0
G_AC_I: C602.1 J600.63 U600.6(S) ; port G_AC_I
GaN_F1: R621.2 ; port GaN_F1
GaN_F2: R625.2 ; port GaN_F2
GaN_F3: R626.2 ; port GaN_F3
HVBUS: R602.2 TP600.1 ; port HVBUS
L100_CS: R600.1 R627.2 ; port L100_CS
L101_CS: R603.1 R628.2 ; port L101_CS
L102_CS: R608.1 R629.2 ; port L102_CS
PFCG_1H: J600.53 ; port PFCG_1H
PFCG_1L: J600.55 ; port PFCG_1L
PFCG_2H: J600.50 ; port PFCG_2H
PFCG_2L: J600.52 ; port PFCG_2L
PFCG_3H: J600.54 ; port PFCG_3H
PFCG_3L: J600.56 ; port PFCG_3L
PRI_FAULT: J600.74 U602.4(INB) ; port PRI_FAULT
PWM1A: J600.49 ; port PWM1A
PWM1B: J600.51 ; port PWM1B
PWM_DEBUG: C617.1 R630.1 ; port PWM_DEBUG
RELAY_CTRL: J600.57 ; port RELAY_CTRL
RELAY_RSET: J600.59 ; port RELAY_RSET
SCI_RX0: J600.76 U602.5(OUTC) ; port SCI_RX0
SCI_TX0: J600.78 U602.3(INA) ; port SCI_TX0
VREFHI: J600.45 ; port VREFHI
NetC601_1: C601.1 J600.15 R600.2
NetC603_2: C603.2 J600.12 R604.1
NetC604_1: C604.1 J600.21 R603.2
NetC607_1: C607.1 J600.25 R608.2
NetC608_1: C608.1 J600.18 R611.1 R613.2
NetC611_1: C611.1 J600.58 R618.1 R621.1 R631.2
NetC612_1: C612.1 J600.60 R620.1 R625.1 R632.2
NetC613_1: C613.1 J600.62 R624.1 R626.1 R633.2
NetC614_1: C614.1 R619.1 R622.1 U601.7(OUT_B)
NetJ600_61: J600.61 R630.2
NetJ602_1: J602.1 U602.14(OUTA)
NetJ602_2: J602.2 U602.12(INC)
NetJ602_3: J602.3 U602.13(OUTB)
NetR601_1: R601.1 R606.1 R611.2 U601.1(OUT_A)
NetR601_2: R601.2 U600.4(A)
NetR602_1: R602.1 R605.2
NetR605_1: R605.1 R607.2
NetR606_2: R606.2 R610.2 R619.2 U600.3(B1) U601.2(IN_A-)
NetR612_1: R612.1 R614.1 R615.2 U601.3(IN_A+)
NetR622_2: R622.2 R623.1 U601.6(IN_B-)
NetR627_1: R627.1 R628.1 R629.1 U601.5(IN_B+)

Not connected (* = marked no-connect by the designer): J600 1* 2* 3* 4* 5* 6* 8* 9* 11* 13* 14* 16* 23* 26* 27* 28* 29* 30* 31* 32* 33* 34* 36* 37* 39* 40* 41* 42* 43* 44* 66* 67* 68* 69* 70* 71* 72* 73* 75* 77* 79* 80* 81* 82* 85* 86* 87* 88* 89* 90* 91* 92* 93* 94* 95* 96* 99* 100* 101* 102* 103* 104* 105* 106* 107* 108* 109* 110* 113* 114* 115* 116* 117* 118* 119* 120; J601 2 MP1 MP2; J602 MP1 MP2; J603 2 MP1 MP2; U600 1(B2)*; U602 6(NC)* 7(EN1)* 10(EN2)* 11(NC)*

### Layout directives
net class MV: NetR602_1

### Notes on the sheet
- Notes:
- 1. C2000 connector pin definition is different from Samtec definition.
- 0k corner frequency
- (near R602) DC OUTPUT FEEDBACK 400V/1.94V
- AC INPUT 400V/1.94V
- Use only R612 or R614.
- C2000 MCU Control Card 120 pin HSEC

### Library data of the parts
C600 C605 C615 C616 = C1608X7R1E105K080AB: as C138 on sheet TIDM-1007_Power
C601 C604 C607 C611-C613 C617 = GRM155R70J103KA01D: CAP, CERM, 0.01uF, 6.3V, +/-10%, X7R, 0402; Manufacturer: MuRata; Polarized: N; CompType: Capacitor; U/M: EA; Cap_F: 0.00000001; Tolerance_%: 10; Value1: Unknown; VDC_V: 6.3; TaMin_C: -55; TaMax_C: 125
C602 = GCM155R71C104KA55D: CAP, CERM, 0.1 µF, 16 V, +/- 10%, X7R, 0402; Manufacturer: MuRata; Polarized: N; CompType: Capacitor; Value: 0.1uF; U/M: EA; Cap_F: 0.0000001; Tolerance_%: 10; Value1: Unknown; VDC_V: 16; Value2: 16V; TaMin_C: -55; TaMax_C: 125; SizeArea_mm2: 0.5; SizeAreaWB_mm2: 3; SizeX_mm: 1; SizeZ_mm: 0.6; AEC Category: Q200
C603 = GRM155R60J104KA01D: CAP, CERM, 0.1uF, 6.3V, +/-10%, X5R, 0402; Manufacturer: MuRata; Polarized: N; CompType: Capacitor; U/M: EA; Cap_F: 0.0000001; Tolerance_%: 10; Value1: Unknown; VDC_V: 6.3; TaMin_C: -55; TaMax_C: 85
C606 C609 C610 = CGA2B2X7R1H471K050BA: CAP, CERM, 470 pF, 50 V,+/- 10%, X7R, AEC-Q200 Grade 1, 0402; Manufacturer: TDK; Polarized: N; CompType: Capacitor; Value: 470pF; U/M: EA; Cap_F: 0.00000000047; Tolerance_%: 10; ESR_ohm: 4.96489; Value1: 4.96489 ohm; VDC_V: 50; Value2: 50V; IRMS_A: 0.228414; TaMin_C: -55; TaMax_C: 125; SizeArea_mm2: 0.5; SizeAreaWB_mm2: 3; SizeX_mm: 1; SizeZ_mm: 0.6; AEC Category: Q200; AEC Qualified: Y
C608 = C1005X5R1A473K050BA: CAP, CERM, 0.047 µF, 10 V, +/- 10%, X5R, 0402; Manufacturer: TDK; Polarized: N; CompType: Capacitor; Value: 0.047uF; U/M: EA; Cap_F: 0.000000047; Tolerance_%: 10; Value1: Unknown; Value2: 10V; TaMin_C: -55; TaMax_C: 85; SizeArea_mm2: 0.5; SizeAreaWB_mm2: 3; SizeX_mm: 1; SizeZ_mm: 0.6; AEC Category: Q200
C614 = GRM1555C1E470JA01D: CAP, CERM, 47 pF, 25 V, +/- 5%, C0G/NP0, 0402; Manufacturer: MuRata; Polarized: N; CompType: Capacitor; Value: 47pF; U/M: EA; Cap_F: 0.000000000047; Tolerance_%: 5; Value1: Unknown; VDC_V: 25; Value2: 25V; TaMin_C: -55; TaMax_C: 125; SizeArea_mm2: 0.5; SizeAreaWB_mm2: 3; SizeX_mm: 1; SizeZ_mm: 0.6; AEC Category: Q200
J600 = controlCARD-120HSEC: C2000 controlCARD-120HSEC connector, SMT; Manufacturer: Samtec; SymbolCreator: a0412235; Note: The pin numbering does not match Samtec datasheet
J601-J603 = DF59-3S-2V(51): Receptacle, 2mm, 3x1, Gold, Natural, SMT; Manufacturer: Hirose Electric Co. Ltd.; SymbolCreator: Altium; Pitch_mm: 2; Gender: Female; Row_Count: 1; Current_A: 3; Voltage_V: 230; Cert_UL: Y
R600 R603 R608 R630 = CRCW04021K40FKED: RES, 1.40k ohm, 1%, 0.063W, 0402; Manufacturer: Vishay-Dale; CompType: Resistor; Res_ohm: 1400; Value_Code: 1k40; Tolerance_%: 1; Power_W: 0.063; VDC_V: 50; TempCo: 100 ppm/C; EIA_Code: E96; U/M: EA
R601 R606 = CRCW04023K57FKED: RES, 3.57 k, 1%, 0.063 W, 0402; Manufacturer: Vishay-Dale; CompType: Resistor; Value: 3.57k; Res_ohm: 3570; Value_Code: 3k57; Tolerance_%: 1; Power_W: 0.063; Value2: 0.063W; VDC_V: 50; TempCo: 100 ppm/C; SizeArea_mm2: 0.5; SizeZ_mm: 0.6; EIA_Code: E96; U/M: EA; AEC Category: Q200; Green_Lifecycle: Active; Green_REACh: Passed
R602 R605 R607 = RT0805BRD07348KL: as R100 on sheet TIDM-1007_Power
R604 = CRCW040210K0JNED: RES, 10k ohm, 5%, 0.063W, 0402; Manufacturer: Vishay-Dale; CompType: Resistor; Res_ohm: 10000; Value_Code: 10k0; Tolerance_%: 5; Power_W: 0.063; VDC_V: 50; TempCo: 200 ppm/C; EIA_Code: E24; U/M: EA
R609 = CRCW08057K50FKEA: RES, 7.50 k, 1%, 0.125 W, 0805; Manufacturer: Vishay-Dale; CompType: Resistor; Value: 7.50k; Res_ohm: 7500; Value_Code: 7k50; Tolerance_%: 1; Power_W: 0.125; Value2: 0.125W; VDC_V: 150; TempCo: 100 ppm/C; SizeArea_mm2: 2.5; SizeX_mm: 2; SizeY_mm: 1.25; SizeZ_mm: 1.45; EIA_Code: E96; U/M: EA; AEC Category: Q200
R610 R619 = CRCW04021K00FKED: RES, 1.00 k, 1%, 0.063 W, 0402; Manufacturer: Vishay-Dale; CompType: Resistor; Value: 1.00k; Res_ohm: 1000; Value_Code: 1k00; Tolerance_%: 1; Power_W: 0.063; Value2: 0.063W; VDC_V: 50; TempCo: 100 ppm/C; SizeArea_mm2: 0.5; SizeZ_mm: 0.6; EIA_Code: E96; U/M: EA; AEC Category: Q200
R611 = CRCW040233R2FKED: RES, 33.2, 1%, 0.063 W, 0402; Manufacturer: Vishay-Dale; CompType: Resistor; Value: 33.2; Value_Code: 33R2; Tolerance_%: 1; Power_W: 0.063; Value2: 0.063W; VDC_V: 50; TempCo: 100 ppm/C; SizeArea_mm2: 0.5; SizeZ_mm: 0.6; EIA_Code: E96; U/M: EA; AEC Category: Q200; Green_Lifecycle: Active; Green_REACh: Passed
R612 R615 R622 R623 R627-R629 = CRCW040210K0FKED: RES, 10.0 k, 1%, 0.063 W, 0402; Manufacturer: Vishay-Dale; CompType: Resistor; Value: 10.0k; Res_ohm: 10000; Value_Code: 10k0; Tolerance_%: 1; Power_W: 0.063; Value2: 0.063W; VDC_V: 50; TempCo: 100 ppm/C; SizeArea_mm2: 0.5; SizeZ_mm: 0.6; EIA_Code: E96; U/M: EA; AEC Category: Q200
R613 = ERA-2AEB4871X: RES, 4.87 k, 0.1%, 0.062 W, AEC-Q200 Grade 0, 0402; Manufacturer: Panasonic; CompType: Resistor; Value: 4.87k; Res_ohm: 4870; Value_Code: 4k87; Tolerance_%: 0.1; Power_W: 0.062; Value2: 0.062W; VDC_V: 25; TempCo: 25 ppm/C; EIA_Code: E192; U/M: EA; AEC Category: Q200; AEC Qualified: Y; AEC Grade: 0
R614 R621 R625 R626 = CRCW04020000Z0ED: RES, 0, 5%, 0.063 W, 0402; Manufacturer: Vishay-Dale; CompType: Resistor; Value: 0; Value_Code: 0000; Tolerance_%: 5; Power_W: 0.063; Value2: 0.063W; VDC_V: 50; TempCo: 200 ppm/C; SizeArea_mm2: 0.5; SizeX_mm: 1; SizeZ_mm: 0.6; EIA_Code: E24; U/M: EA; AEC Category: Q200
R616 R617 = CRCW04027K50FKED: RES, 7.50 k, 1%, 0.063 W, 0402; Manufacturer: Vishay-Dale; CompType: Resistor; Value: 7.50k; Res_ohm: 7500; Value_Code: 7k50; Tolerance_%: 1; Power_W: 0.063; Value2: 0.063W; VDC_V: 50; TempCo: 100 ppm/C; SizeArea_mm2: 0.5; SizeZ_mm: 0.6; EIA_Code: E96; U/M: EA; AEC Category: Q200
R618 R620 R624 = CRCW04024K99FKED: RES, 4.99 k, 1%, 0.063 W, 0402; Manufacturer: Vishay-Dale; CompType: Resistor; Value: 4.99k; Res_ohm: 4990; Value_Code: 4k99; Tolerance_%: 1; Power_W: 0.063; Value2: 0.063W; VDC_V: 50; TempCo: 100 ppm/C; SizeArea_mm2: 0.5; SizeZ_mm: 0.6; EIA_Code: E96; U/M: EA; AEC Category: Q200
R631-R633 = CRCW04029K31FKED: RES, 9.31 k, 1%, 0.063 W, 0402; Manufacturer: Vishay-Dale; CompType: Resistor; Value: 9.31k; Res_ohm: 9310; Value_Code: 9k31; Tolerance_%: 1; Power_W: 0.063; Value2: 0.063W; VDC_V: 50; TempCo: 100 ppm/C; SizeArea_mm2: 0.5; SizeZ_mm: 0.6; EIA_Code: E96; U/M: EA; AEC Category: Q200
TP600-TP609 = 0312-0-15-15-34-27-10-0: as TP104 on sheet TIDM-1007_Power
U600 = SN74LVC1G3157DRYR: SINGLE-POLE DOUBLE-THROW ANALOG SWITCH, DRY0006A; Manufacturer: Texas Instruments; SymbolCreator: a0799628; CompType: IC; U/M: EA
U601 = OPA2376AIDG4: Precision, Low Noise, Low Quiescent Current Operational Amplifier, 2 to 5.5 V, -40 to 125 degC, 8-pin SOIC (D0008A), Green (RoHS & no Sb/Br); Manufacturer: Texas Instruments; Alternate PartNumber: Equivalent; CMRR(Min)(dB): 76; IIB(Max)(pA): 10; Iq per channel(Max)(mA): 0.95; Number of Channels: 2; Offset Drift(Typ)(uV/C): 0.32; Sub Family: Low Input Bias Current Amp (<=10pA), Low Noise Amp (<=10nV/rtHz), Low Offset Voltage Amplifier (<=500uV), Low Supply Voltage Amplifier (<=2.7V), Precision Amplifier; Total Supply Voltage(Max)(+5V is 5, +/-5V is 10): 5.5; Vio (25C)(Max)(mV): 0.025; Vn at 1kHz(Typ)(nV/rtHz): 7.5
U602 = ISO7831DWR: High-Performance, 8000 VPK Reinforced Triple Digital Isolator, DW0016B; Manufacturer: Texas Instruments; SymbolCreator: Altium; SizeArea_mm2: 107.12; SizeAreaWB_mm2: 152.52; SizeX_mm: 10.4; SizeY_mm: 10.3; SizeZ_mm: 2.65; CompType: IC; U/M: EA

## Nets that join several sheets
EARTH: TIDM-1007_Power (5 pins), TIDM-1007_Control (TP603.1)
PGND: TIDM-1007_Power (53 pins), TIDM-1007_Control (46 pins)
3V3: TIDM-1007_Power (17 pins), TIDM-1007_Control (R612.2)
5Vp: TIDM-1007_Power (6 pins), TIDM-1007_Control (14 pins)
12Vp: TIDM-1007_Power (9 pins), TIDM-1007_Control (J601.1 TP604.1)
AC_CUR_FAULT: TIDM-1007_Power (C129.2 R125.2 U101.13), TIDM-1007_Control (J600.64)
AC_CUR_SENSE: TIDM-1007_Power (U101.12), TIDM-1007_Control (R610.1)
AC_CUR_VREF: TIDM-1007_Power (C128.1 U101.10), TIDM-1007_Control (R604.2 R614.2)
ACL_SENSE: TIDM-1007_Power (R100.1), TIDM-1007_Control (C610.1 J600.20 R617.2)
ACN_SENSE: TIDM-1007_Power (R123.1), TIDM-1007_Control (C609.1 J600.17 R616.2)
GaN_F1: TIDM-1007_Power (J101.3), TIDM-1007_Control (R621.2)
GaN_F2: TIDM-1007_Power (J102.3), TIDM-1007_Control (R625.2)
GaN_F3: TIDM-1007_Power (J103.3), TIDM-1007_Control (R626.2)
HVBUS: TIDM-1007_Power (20 pins), TIDM-1007_Control (R602.2 TP600.1)
L100_CS: TIDM-1007_Power (U100.7), TIDM-1007_Control (R600.1 R627.2)
L101_CS: TIDM-1007_Power (U102.7), TIDM-1007_Control (R603.1 R628.2)
L102_CS: TIDM-1007_Power (U104.7), TIDM-1007_Control (R608.1 R629.2)
PFCG_1H: TIDM-1007_Power (J101.1), TIDM-1007_Control (J600.53)
PFCG_1L: TIDM-1007_Power (J101.2), TIDM-1007_Control (J600.55)
PFCG_2H: TIDM-1007_Power (J102.1), TIDM-1007_Control (J600.50)
PFCG_2L: TIDM-1007_Power (J102.2), TIDM-1007_Control (J600.52)
PFCG_3H: TIDM-1007_Power (J103.1), TIDM-1007_Control (J600.54)
PFCG_3L: TIDM-1007_Power (J103.2), TIDM-1007_Control (J600.56)
PWM1A: TIDM-1007_Power (R127.2), TIDM-1007_Control (J600.49)
PWM1B: TIDM-1007_Power (R128.2), TIDM-1007_Control (J600.51)
RELAY_CTRL: TIDM-1007_Power (C120.1 Q102.1 R122.2), TIDM-1007_Control (J600.57)

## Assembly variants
001: not fitted R132 R133 R134 R612 R613 R615 R619 U602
